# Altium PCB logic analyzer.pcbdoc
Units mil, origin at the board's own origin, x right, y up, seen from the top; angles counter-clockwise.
Board outline 1771.65 x 984.25 mil, 2 copper layers (Top Layer, Bottom Layer); 46 components, 39 nets, 224 pads, 64 vias.
Unrouted connection lines stored in the file: 47.
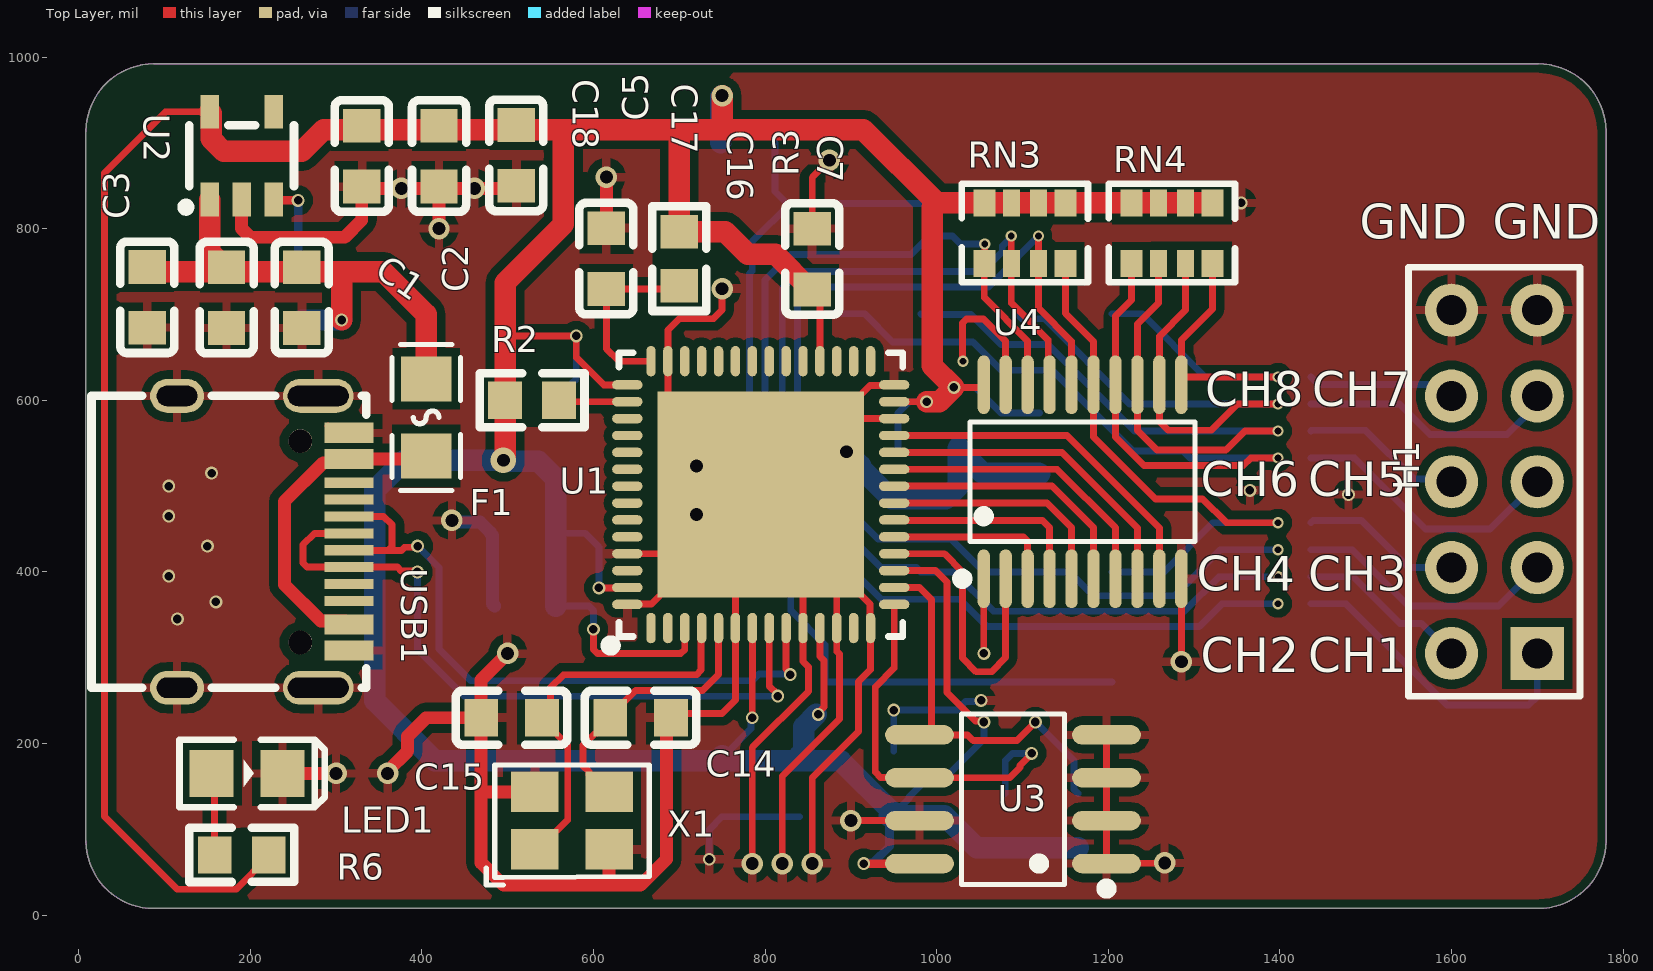
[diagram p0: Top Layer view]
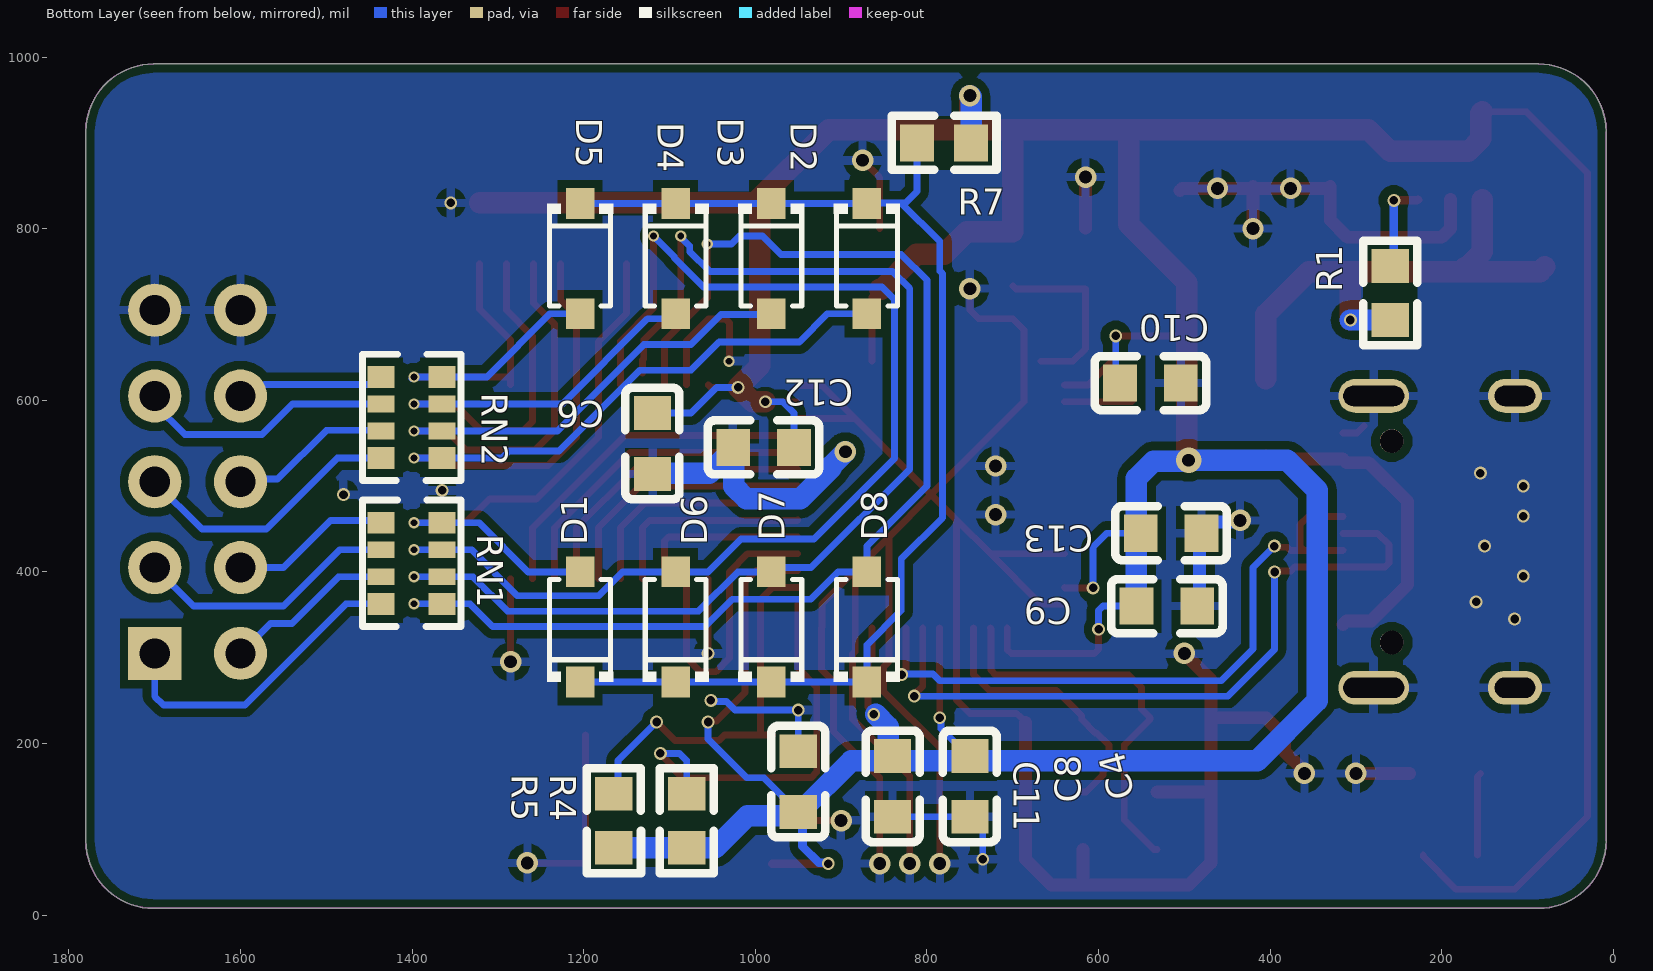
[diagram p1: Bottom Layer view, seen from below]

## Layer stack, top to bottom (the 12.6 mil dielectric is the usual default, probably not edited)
Top Solder: solder mask 0.4, Solder Resist, Dk 3.5
Top Layer: signal copper 1.4
Dielectric1: dielectric 12.6, FR-4, Dk 4.8
Bottom Layer: signal copper 1.4
Bottom Solder: solder mask 0.4, Solder Resist, Dk 3.5

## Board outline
8.51,86.42 8.51,913.2 cw(c87.25,913.2) 87.25,991.94 1701.43,991.94 cw(c1701.43,913.2) 1780.17,913.2 1780.17,86.42 cw(c1701.43,86.42) 1701.43,7.68 87.25,7.68 cw(c87.25,86.42)

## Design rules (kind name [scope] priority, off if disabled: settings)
Clearance [All] p1: gap=10 ignorepadtopadclearanceinfootprint=TRUE except(0: Arc-Hole Track-Hole SMDPad-Hole THPad-Hole Via-Hole Fill-Hole Poly-Hole Region-Hole Text-Hole; 6: Arc-SMDPad Track-SMDPad)
PolygonConnect [All] p1: connectstyle=Relief reliefconductorwidth=10 reliefentries=4 polygonreliefangle="90 Angle" airgapwidth=10
RoutingVias [All] p1: holewidth=28 width=50 viastyle="Through Hole" minholewidth=5 minwidth=10 maxholewidth=99 maxwidth=100
SolderMaskExpansion [All] p1: expansion=4 istentingtop=FALSE
Width [All] p1: maxlimit=100 minlimit=6 preferedwidth=10 minimp=50.000000 maximp=50.000000 favimp=50.000000
30 further rules are at their usual default settings.

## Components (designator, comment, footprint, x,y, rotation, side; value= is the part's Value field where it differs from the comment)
C1 "0.1u" C0603 172.5,719.57 r90 top
C2 "0.1u" C0603 260,719.57 r90 top
C3 "0.1u" C0603 80,720 r90 top
C4 "0.1u" C0603 750,150 r90 bottom
C5 "0.1u" C0603 420,884.57 r90 top
C6 "0.1u" C0603 1120,549.57 r90 bottom
C7 "0.1u" C0603 855,764.57 r270 top
C8 "0.1u" C0603 840,150 r90 bottom
C9 "0.1u" C0603 520.43,360 r0 bottom
C10 "0.1u" C0603 539.57,620 r0 bottom
C11 "0.1u" C0603 950,155.43 r270 bottom
C12 "0.1u" C0603 990.43,545 r180 bottom
C13 "0.1u" C0603 515.43,445 r0 bottom
C14 "0.1u" C0603 655,230 r180 top
C15 "0.1u" C0603 504.57,230 r0 top
C16 "0.1u" C0603 615,765 r270 top
C17 "0.1u" C0603 510,885.43 r270 top
C18 "0.1u" C0603 330,884.57 r270 top
D1 "1N4148W" SOD-123_L3.1-W1.7-LS3.7-RD 1204.29,335.83 r90 bottom
D2 "1N4148W" SOD-123_L3.1-W1.7-LS3.7-RD 870,765 r270 bottom
D3 "1N4148W" SOD-123_L3.1-W1.7-LS3.7-RD 981.43,765 r270 bottom
D4 "1N4148W" SOD-123_L3.1-W1.7-LS3.7-RD 1092.86,765 r270 bottom
D5 "1N4148W" SOD-123_L3.1-W1.7-LS3.7-RD 1204.29,765 r270 bottom
D6 "1N4148W" SOD-123_L3.1-W1.7-LS3.7-RD 1092.86,335.83 r90 bottom
D7 "1N4148W" SOD-123_L3.1-W1.7-LS3.7-RD 981.43,335.83 r90 bottom
D8 "1N4148W" SOD-123_L3.1-W1.7-LS3.7-RD 870,335.83 r90 bottom
F1 "MF-PSMF075X-2" F0805 405,580 r90 top
H1 "HDR-F-2.54_2x5" HDR-F-2.54_2X5 1650,505 r90 top
LED1 "LED-0805_R" LED0805_RED 196.35,165 r0 top
R1 "10K" R0603 260,725 r90 bottom
R2 "10k" R0603 528.5,600 r0 top
R3 "1k" R0603 700,765 r90 top
R4 "10K" R0603 1080,110 r270 bottom
R5 "10K" R0603 1165,110 r270 bottom
R6 "1k" R0603 190,70 r0 top
R7 "1k" R0603 780,900 r180 bottom
RN1 "100R" RES-ARRAY-SMD_0603-8P-L3.2-W1.6-BL 1400.79,410 r270 bottom
RN2 "100R" RES-ARRAY-SMD_0603-8P-L3.2-W1.6-BL 1400.79,580 r270 bottom
RN3 "470" RES-ARRAY-SMD_0603-8P-L3.2-W1.6-BL 1102.76,794.57 r0 top
RN4 "100K" RES-ARRAY-SMD_0603-8P-L3.2-W1.6-BL 1274.25,794.57 r0 top
U1 "CY7C68013A-56LTXC" QFN-56_L8.0-W8.0-P0.50-TL-EP 795,490 r90 top
U2 "RT9013-33GB" SOT-23-5_L3.0-W1.7-P0.95-LS2.8-BR 190,885 r270 top
U3 "AT24C02" SOP-8_L5.0-W4.0-P1.27-LS6.0-BL 1088.97,135 r90 top
U4 "74HC245PW-Q100J" TSSOP-20_L6.5-W4.4-P0.65-LS6.4-BL 1170,505 r0 top
USB1 "TYPEC-304-BCP16" USB-C-SMD_TYPEC-304-BCP16 215,435 r270 top
X1 "24MHz" OSC-SMD_4P-L3.2-W2.5-BL 575,110 r0 top

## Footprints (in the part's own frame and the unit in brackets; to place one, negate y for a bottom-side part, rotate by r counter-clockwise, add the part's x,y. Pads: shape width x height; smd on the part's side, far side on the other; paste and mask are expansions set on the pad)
C0603 [mm]
  rect 1x1.1 smd: 1(-0.9,0) 2(0.9,0)
  silkscreen extent -1.65,-0.8 1.65,0.8
F0805 [mm]
  rect 1.335x1.5 smd: 1(-1.142,0) 2(1.142,0)
  silkscreen extent -2.16,-1.02 2.16,1.02
HDR-F-2.54_2X5 [mil]
  rect 62x62 hole 35: 1(-200,-50)
  round 62 hole 35: 2(-200,50) 3(-100,-50) 4(-100,50) 5(0,-50) 6(0,50) 7(100,-50) 8(100,50) 9(200,-50) 10(200,50)
  silkscreen extent -250,-100 250,100
LED0805_RED [mil]
  rect 51.2x55.1 smd: 1(-41.35,0) 2(41.35,0)
  silkscreen extent -79,-39 91,39
OSC-SMD_4P-L3.2-W2.5-BL [mm]
  rect 1.4x1.2 smd: 1(-1.1,-0.851) 2(1.1,-0.851) 3(1.1,0.851) 4(-1.1,0.851)
  silkscreen extent -2.54,-1.91 2.29,1.65
QFN-56_L8.0-W8.0-P0.50-TL-EP [mm]
  oval 0.9x0.28 smd: 1(-3.95,3.25) 2(-3.95,2.75) 3(-3.95,2.25) 4(-3.95,1.75) 5(-3.95,1.25) 6(-3.95,0.75) 7(-3.95,0.25) 8(-3.95,-0.25) 9(-3.95,-0.75) 10(-3.95,-1.25) 11(-3.95,-1.75) 12(-3.95,-2.25) 13(-3.95,-2.75) 14(-3.95,-3.25) 29(3.95,-3.25) 30(3.95,-2.75) 31(3.95,-2.25) 32(3.95,-1.75) 33(3.95,-1.25) 34(3.95,-0.75) 35(3.95,-0.25) 36(3.95,0.25) 37(3.95,0.75) 38(3.95,1.25) 39(3.95,1.75) 40(3.95,2.25) 41(3.95,2.75) 42(3.95,3.25)
  oval 0.28x0.9 smd: 15(-3.25,-3.95) 16(-2.75,-3.95) 17(-2.25,-3.95) 18(-1.75,-3.95) 19(-1.25,-3.95) 20(-0.75,-3.95) 21(-0.25,-3.95) 22(0.25,-3.95) 23(0.75,-3.95) 24(1.25,-3.95) 25(1.75,-3.95) 26(2.25,-3.95) 27(2.75,-3.95) 28(3.25,-3.95) 43(3.25,3.95) 44(2.75,3.95) 45(2.25,3.95) 46(1.75,3.95) 47(1.25,3.95) 48(0.75,3.95) 49(0.25,3.95) 50(-0.25,3.95) 51(-0.75,3.95) 52(-1.25,3.95) 53(-1.75,3.95) 54(-2.25,3.95) 55(-2.75,3.95) 56(-3.25,3.95)
  rect 6.1x6.1 smd: 57(0,0)
  silkscreen extent -4.62,-4.2 4.2,4.59
R0603 [mm]
  rect 1x1.1 smd: 1(-0.8,0) 2(0.8,0)
  silkscreen extent -1.55,-0.8 1.55,0.81
RES-ARRAY-SMD_0603-8P-L3.2-W1.6-BL [mm]
  rect 0.65x0.8 smd: 1(-1.2,-0.9) 4(1.2,-0.9) 5(1.2,0.9) 8(-1.2,0.9)
  rect 0.5x0.8 smd: 2(-0.4,-0.9) 3(0.4,-0.9) 6(0.4,0.9) 7(-0.4,0.9)
  silkscreen extent -1.87,-1.45 1.87,1.47
SOD-123_L3.1-W1.7-LS3.7-RD [mm]
  rect 0.91x0.84 smd: 1(-1.63,0) 2(1.63,0)
  silkscreen extent -1.63,-0.98 1.4,0.98
SOP-8_L5.0-W4.0-P1.27-LS6.0-BL [mil]
  oval 22.6x80.14 smd: 1(-75,-108.97) 2(-25,-108.97) 3(25,-108.97) 4(75,-108.97) 5(75,108.97) 6(25,108.97) 7(-25,108.97) 8(-75,108.97)
  silkscreen extent -110,-115 99,60
SOT-23-5_L3.0-W1.7-P0.95-LS2.8-BR [mm]
  rect 1x0.55 smd: 1(1.3,-0.95) 2(1.3,0) 3(1.3,0.95) 4(-1.3,0.95) 5(-1.3,-0.95)
  silkscreen extent -0.9,-1.78 1.65,1.55
TSSOP-20_L6.5-W4.4-P0.65-LS6.4-BL [mm]
  oval 0.364x1.742 smd: 1(-2.925,-2.871) 2(-2.275,-2.871) 3(-1.625,-2.871) 4(-0.975,-2.871) 5(-0.325,-2.871) 6(0.325,-2.871) 7(0.975,-2.871) 8(1.625,-2.871) 9(2.275,-2.871) 10(2.925,-2.871) 11(2.925,2.871) 12(2.275,2.871) 13(1.625,2.871) 14(0.975,2.871) 15(0.325,2.871) 16(-0.325,2.871) 17(-0.975,2.871) 18(-1.625,2.871) 19(-2.275,2.871) 20(-2.925,2.871)
  silkscreen extent -3.71,-3.02 3.33,1.77
USB-C-SMD_TYPEC-304-BCP16 [mm]
  oval 1x2.1 hole 0.6 slot 1.8 at 90 deg: 13(-4.32,1.633) 14(4.32,1.633)
  oval 1x1.6 hole 0.6 slot 1.2 at 90 deg: 15(-4.32,-2.547) 16(4.32,-2.547)
  rect 0.6x1.45 smd: A1B12(-3.225,2.547) A4B9(-2.45,2.547) B1A12(3.22,2.547) B4A9(2.45,2.547)
  rect 0.3x1.45 smd: A5(-1.25,2.547) A6(-0.25,2.547) A7(0.25,2.547) A8(1.25,2.547) B5(1.75,2.547) B6(0.75,2.547) B7(-0.75,2.547) B8(-1.75,2.547)
  round 0.7 hole 0.7 unplated: ""(-2.98,1.102) ""(2.98,1.102)
  silkscreen extent -4.32,-5.08 4.32,3.05

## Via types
v1: diameter 15, hole 10, Top Layer to Bottom Layer, 31 vias
v2: diameter 25, hole 15, Top Layer to Bottom Layer, 20 vias
v3: diameter 13, hole 8, Top Layer to Bottom Layer, 12 vias
v4: diameter 30, hole 15, Top Layer to Bottom Layer, 1 vias

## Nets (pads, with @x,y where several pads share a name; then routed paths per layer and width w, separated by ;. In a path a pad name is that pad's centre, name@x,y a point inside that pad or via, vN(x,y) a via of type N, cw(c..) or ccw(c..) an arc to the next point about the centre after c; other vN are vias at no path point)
3V3: C4.2 C5.2 C6.2 C7.2 C8.2 C9.2 C10.2 C11.2 C12.2 C13.2 C17.1 C18.1 R2.1 R3.2 R4.2 R5.2 R6.2 R7.2 RN3.5 RN3.6 RN3.7 RN3.8 RN4.5 RN4.6 RN4.7 RN4.8 U1.3 U1.7 U1.11 U1.17 U1.27 U1.32 U1.43 U1.55 U2.5 U3.8 U4.20 | length 6851.9
  Top Layer w8: U2.5 101.19,936.19 30,865 30,115 115,30 183.46,30 221.5,68.03 R6.2 ; 497.01,668.51 503.51,675 v1(580,675) 580,650 612.05,617.95 U1.43 ; v1(600,333.05) 600,309.69 604.69,305 701.73,305 706.42,309.69 U1.3 ; v1(606.3,381.3) 639.06,381.3 U1.55 ; v1(785,230) 785,276.98 785.16,277.14 U1.7 ; C7.2 863.9,720.23 U1.32 ; v1(861.95,233.84) 861.95,235.74 868.82,242.61 868.82,296.63 863.9,301.56 U1.11 ; U1.17 998.58,401.42 1012,388 1012,259.58 1045.24,226.34 1053.66,226.34 v1(1055,225) ; U1.27 v1(988.27,598.27) ; v1(1020,615) 1051.92,615 1054.84,617.92 U4.20
  Top Layer w10: v1(915,60) U3.8
  Top Layer w25: U2.5 154.28,934.51 154.28,904.64 168.92,890 260,890 285.43,915.43 330,915.43 420,915.43 505,915.43 565,915.43 ; v4(495,530) 497.01,532.01 R2.1 497.01,668.51 497.01,737.01 565,805 565,915.43 ; v2(750,955) 750,915.43 ; C7.2 853.03,729.13 812.17,770 780,770 753.5,796.5 R3.2 700,910.86 704.57,915.43 ; v1(988.27,598.27) 1003.27,598.27 v1(1020,615) 995,640 995,825 1000,830 ; RN4.5 RN4.6 RN4.7 RN4.8 RN3.5 RN3.6 RN3.7 RN3.8 1000,830 ; 565,915.43 704.57,915.43 ; 704.57,915.43 750,915.43 ; 750,915.43 914.56,915.43 1000,830
  Bottom Layer w8: C13.2 555.87,445 590,445 606.3,428.7 v1(606.3,381.3) ; C9.2 595,360 600,355 v1(600,333.05) ; C10.2 580,625 v1(580,675) ; C4.2 751.97,185.43 783.66,217.13 783.66,228.66 v1(785,230) ; C11.2 951.97,120 967.65,135.68 967.65,137.65 990,160 1010,160 1055,205 v1(1055,225) ; C12.2 955,585 968.27,598.27 v1(988.27,598.27) ; v1(1020,615) 1045,615 1075,585 C6.2
  Bottom Layer w10: v1(915,60) 915.91,60.91 925.91,60.91 945,80 C11.2@945,115
  Bottom Layer w25: C9.2 555.87,445 555.87,509.13 535.96,529.04 495.96,529.04 v4(495,530) 380,530 345,495 345,250 415,180 C4.2@755.43,180 ; R7.2 748.5,953.5 v2(750,955) ; C4.2 C4.2@755.43,180 ; C8.2@840,180 888.03,180 948.03,120 C11.2 ; v1@859.64,233.84 845,219.2 845,190.43 C8.2 834.57,180 C4.2@755.43,180 ; C11.2@945,115 945.85,115.85 1009.15,115.85 1046.49,78.5 R4.2 R5.2
+5V: C1.2 C2.2 C3.2 F1.2 R1.1 U2.1 | length 615.6
  Top Layer w25: C3.2 85.43,750 310,750 ; U2.1 152.6,772.93 170.53,755 C1.2 ; v1(306.49,693.51) 306.49,746.49 310,750 ; F1.2 405,700 355,750 310,750
  Bottom Layer w25: R1.1 v1(306.49,693.51)
D1_1: D1.1 D2.1 D3.1 D4.1 D5.1 D6.1 D7.1 D8.1 R7.1 | length 1404.2
  Bottom Layer w8: R7.1 811.49,843.51 825,830 830,830 ; D1.1 D6.1 D7.1 D8.1 870,315 830,355 830,415 782,463 782,747.46 785,750.46 785,785 830,830 ; D5.1 D4.1 D3.1 871.65,829.17 870.83,830 830,830
DN: U1.9 USB1.A7 USB1.B7 | length 782.2
  Top Layer w8: USB1.A7 315.45,425 360.31,425 ; USB1.B7 355.47,464.53 365,455 365,429.69 360.31,425 ; v1(395,430) 393.66,428.66 379.97,428.66 376.31,425 360.31,425 ; U1.9 824.53,286.96 829.32,282.17 v1(829.32,280.27)
  Bottom Layer w8: v1(395,430) 420,405 420,310 457,273 785,273 792.95,280.95 828.65,280.95 v1(829.32,280.27)
DP: U1.8 USB1.A6 USB1.B6 | length 834.5
  Top Layer w8: USB1.A6 274.75,444.85 261.5,431.59 261.5,410.16 266.19,405.47 USB1.B6 371.5,405.47 375.84,401.14 393.46,401.14 v1(394.8,399.8) ; U1.8 804.84,267.05 814.8,257.1 v1(814.8,255.2)
  Bottom Layer w8: v1(394.8,399.8) 395,399.59 395,309.54 449.54,255 814.59,255 v1(814.8,255.2)
GND: C1.1 C2.1 C3.1 C4.1 C5.1 C6.1 C7.1 C8.1 C9.1 C10.1 C11.1 C12.1 C13.1 C14.1 C15.1 C16.1 C17.2 C18.2 H1.9 H1.10 LED1.2 U1.6 U1.10 U1.12 U1.14 U1.26 U1.28 U1.41 U1.53 U1.56 U1.57 U2.2 U3.1 U3.2 U3.3 U3.4 U3.7 U4.1 U4.10 U4.19 USB1.13 USB1.14 USB1.15 USB1.16 USB1.A1B12 USB1.B1A12 X1.2 X1.4 | length 5519.1
  Top Layer w8: USB1.13 USB1.13@290.75,593.6 ; USB1.A1B12@290.75,569.78 298.56,561.97 USB1.A1B12 ; U1.56 640.05,362.61 667.61,362.61 U1.57@726.1,421.1 ; U1.53 U1.57@726.1,421.1 ; C14.1@685,224.57 C14.1 695.43,235 750,235 765.47,250.47 U1.6 U1.57@765.47,460.47 ; v2(750,730) 750,705 740,695 700,695 686.73,681.73 U1.41 686.73,598.27 U1.57 ; v2(785,60) 785,195 850.82,260.82 850.82,289.18 844.21,295.79 U1.10 U1.57@844.21,440.79 ; v2(820,60) 820,161.49 886.82,228.31 886.82,304.09 883.58,307.33 U1.12 U1.57@883.58,401.42 ; v2@855,55 855,160 908.97,213.97 908.97,271.92 922.95,285.9 U1.14 922.39,335.05 922.39,362.61 U1.57@883.58,401.42 ; C7.1 855,859.39 875,879.39 v2(875,879.69) ; v2@895,115 v2(900,110) U3.7 ; U1.26 U1.57@883.58,578.58 ; U1.28 949.95,617.39 922.39,617.39 U1.57@883.58,578.58 ; v3(1030.51,645.51) 1030,646.01 1030,690.09 1034.69,694.77 1054.77,694.77 1080.43,669.11 U4.19 ; U4.1 1054.92,391.89 1054.92,305.08 v1(1055,305) ; U3.4 U3.3 U3.2 U3.1 1198.33,60.4 1265.4,60.4 v2(1265.79,60.79) ; v2@1285,295 v2(1285.16,295.16) U4.10 ; U1.57@726.1,421.1 U1.57@765.47,460.47 ; U1.57@765.47,460.47 U1.57 ; U1.57 U1.57@844.21,440.79 ; U1.57 U1.57@883.58,578.58 ; U1.57@844.21,440.79 U1.57@883.58,401.42
  Top Layer w15: U2.2 190,800 200,790 310,790 330,810 C18.2 332.28,846.85 C5.1@420,846.85 ; LED1.2 v2(300,165) ; v2(360,165) 360,167.58 383.46,191.04 383.46,208.46 405,230 C15.1 ; v2(420,800) C5.1@420,846.85 ; C5.1 C5.1@420,846.85 ; v2(500,305) 469.13,274.13 C15.1 ; C17.2@505,844.57 502.72,846.85 C5.1@420,846.85 ; X1.4 471.06,143.51 469.13,145.43 ; C16.1 v2(615,860) ; X1.2 618.31,36.69 620,35 ; C14.1@685,224.57 685,65 655,35 620,35 ; 469.13,145.43 C15.1 ; 469.13,145.43 469.13,60.87 495,35 620,35
  Bottom Layer w8: v1(735,65) 735,99.57 C4.1 C8.1 ; C11.1 v1(950,238.77) 1023.77,238.77 1033.81,248.81 1050.49,248.81 v1(1051.83,250.15) ; C12.1@1025.87,543.03 C12.1
  Bottom Layer w15: v2(435,460) 436.91,458.09 467.81,458.09 480,445.9 C13.1 482.5,442.5 482.5,362.5 C9.1
  Bottom Layer w25: v2(895,540) 911.33,523.67 911.33,521.17 947.5,485 1010.36,485 1025,499.64 1025,544.13 C12.1 ; C12.1@1025.87,543.03 1053.9,515 1119.13,515 C6.1
  other v1: 115,345 160,365 105,395 150,430 105,465 1480,490 1365,495 105,500 155,515 1355,830
  other v2: 855,60 720,466.67 720,523.33 376.14,846.85 461.36,846.85
IN0: D8.2 RN1.5 RN3.1 U4.18 | length 1400.8
  Top Layer w8: v3(1056.02,782.06) 1056.02,759.65 RN3.1 1055.52,719.48 1106.02,668.98 U4.18
  Bottom Layer w8: v3(1056.02,782.06) 1027.86,782.06 1018.36,791.55 991.55,791.55 970,770 830,770 800,740 800,500 870,430 D8.2 903.77,400 935.72,368.04 1026.96,368.04 1058.91,336.09 1306.09,336.09 1332.76,362.76 RN1.5 v3(1397.77,362.76)
IN1: D7.2 RN1.6 RN3.2 U4.17 | length 1348.4
  Top Layer w8: v3(1087.01,791.55) RN3.2 1087.01,713.45 1130,670.46 1130,648.48 1131.61,646.87 U4.17@1131.61,631.59
  Bottom Layer w8: v3(1087.01,791.55) 1087.01,790.19 1076.52,779.71 1076.52,773.56 1052.96,750 840,750 820,730 820,520 935,405 976.43,405 D7.2 1020.46,400 1066.37,354.09 1289.09,354.09 1329.25,394.25 RN1.6 v3(1397.77,394.25)
IN2: D6.2 RN1.7 RN3.3 U4.16 | length 1335.3
  Top Layer w8: v3(1118.51,791.55) RN3.3 1118.51,707.4 1157.2,668.71 U4.16
  Bottom Layer w8: v3(1118.51,791.55) 1094.52,767.56 1094.52,766.11 1060.42,732 852.58,732 838,717.42 838,532 931.66,438.34 1016.66,438.34 1055,400 D6.2 1155,400 1182.91,372.09 1277.09,372.09 1330.75,425.75 RN1.7 v3(1397.77,425.75)
IN3: D1.2 RN1.8 RN3.4 U4.15 | length 689.1
  Top Layer w8: RN3.4 1150,701.37 1182.8,668.57 U4.15 1182.8,557.21 1255,485 1310,485 1337.76,457.24 v3(1397.76,457.24)
  Bottom Layer w8: D1.2 1265,400 1322.24,457.24 RN1.8 v3(1397.76,457.24)
IN4: D2.2 RN2.5 RN4.1 U4.14 | length 1013.9
  Top Layer w8: RN4.1 1227.01,717.01 1208.39,698.39 U4.14 1208.39,557.07 1241.46,524 1357.33,524 1366.09,532.76 v3(1397.77,532.76)
  Bottom Layer w8: D2.2 915.85,700.83 948.77,667.91 1042.09,667.91 1075,635 1134.54,635 1228.91,540.63 1287.32,540.63 1295.2,532.76 v3(1397.77,532.76)
IN5: D3.2 RN2.6 RN4.2 U4.13 | length 859.8
  Top Layer w8: RN4.2 1258.5,713.5 1233.98,688.98 1233.98,564.82 1256.8,542 1337,542 1359.25,564.25 v3(1397.77,564.25)
  Bottom Layer w8: D3.2 982.26,700 1040,700 1075,665 1130,665 1230.75,564.25 RN2.6 v3(1397.77,564.25)
IN6: D4.2 RN2.7 RN4.3 U4.12 | length 700
  Top Layer w8: RN4.3 1290,705 1259.57,674.57 1259.57,575.43 1270,565 1320,565 1350.75,595.75 v3(1397.77,595.75)
  Bottom Layer w8: D4.2 1098.68,695 1125.46,695 1224.71,595.75 RN2.7 v3(1397.77,595.75)
IN7: D5.2 RN2.8 RN4.4 U4.11 | length 497.1
  Top Layer w8: U4.11 U4.11@1285.16,624.31 ; RN4.4 1321.49,706.49 1285.16,670.16 U4.11@1285.16,624.31 ; v3(1397.76,627.24) 1288.08,627.24 U4.11@1285.16,624.31
  Bottom Layer w8: D5.2 1239.17,700.83 1312.76,627.24 RN2.8 v3(1397.76,627.24) v3@1400,625
P0: H1.1 RN1.4 | length 366.7
  Bottom Layer w8: RN1.4 1477.24,362.76 1595,245 1690,245 1700,255 H1.1
P1: H1.2 RN1.3 | length 200.7
  Bottom Layer w8: RN1.3 1485.75,394.25 1540,340 1565,340 H1.2
P2: H1.3 RN1.2 | length 309.7
  Bottom Layer w8: RN1.2 1484.25,425.75 1550,360 1655,360 H1.3
P3: H1.4 RN1.1 | length 187.7
  Bottom Layer w8: RN1.1 1438.97,460 1495,460 1550,405 H1.4
P4: H1.5 RN2.4 | length 320.8
  Bottom Layer w8: RN2.4 1487.24,532.76 1570,450 1645,450 H1.5
P5: H1.6 RN2.3 | length 188.9
  Bottom Layer w8: RN2.3 1436.97,565 1500,565 1557,508 1597,508 H1.6
P6: H1.7 RN2.2 | length 303.1
  Bottom Layer w8: RN2.2 1539.25,595.75 1575,560 1665,560 1700,595 H1.7
P7: H1.8 RN2.1 | length 173
  Bottom Layer w8: RN2.1 1445.01,618.45 1571.94,618.45 1585.39,605 H1.8
R6_1: LED1.1 R6.1 | length 96.5
  Top Layer w8: LED1.1 158.51,161.49 R6.1
SCL: R4.1 U1.15 U3.6 | length 475.6
  Top Layer w8: U1.15 950.51,288 928.44,265.93 928.44,166.65 934.69,160.41 979.59,160.41 U3.6 1085,160 1097.19,172.19 1097.19,174.34 1110.71,187.87 v1(1110.71,188.39)
  Bottom Layer w8: R4.1 1080,180 1088.39,188.39 v1(1110.71,188.39)
SDA: R5.1 U1.16 U3.5 | length 458.1
  Top Layer w8: U1.16 980,381.73 994,367.73 994,210.74 U3.5@993.26,210 ; U3.5 U3.5@993.26,210 ; v1(1115,225) 1093.5,203.5 1042.62,203.5 1036.12,210 U3.5@993.26,210
  Bottom Layer w8: v1(1115,225) 1160,180 1160,146.49 R5.1
U1_4: C15.2 U1.4 X1.1 | length 456.5
  Top Layer w8: X1.1 535.63,76.5 570,110.87 570,198.03 540,228.03 C15.2 550,240 550,265 565,280 720,280 725.52,285.52 725.52,333.91 U1.4
U1_5: C14.2 U1.5 X1.3 | length 317.7
  Top Layer w8: X1.3 614.37,143.51 594.75,163.13 594.75,167.07 588,173.81 588,198 602.35,212.35 603.88,212.35 619.57,228.03 619.57,231.97 649.25,261.65 727.11,261.65 745.79,280.33 U1.5
U1_18: U1.18 U4.2 | length 344.5
  Top Layer w8: U1.18 1008.9,421.1 1030,400 1030,299.59 1046.09,283.5 1063.91,283.5 1080.43,300.03 U4.2
U1_19: U1.19 U4.3 | length 201.6
  Top Layer w8: U1.19 1101.34,440.79 1106.02,436.1 U4.3
U1_20: U1.20 U4.4 | length 244.5
  Top Layer w8: U1.20 950.98,460 1123.45,460 1131.61,451.84 U4.4
U1_21: U1.21 U4.5 | length 278.2
  Top Layer w8: U1.21 1128.75,480.16 1157.2,451.7 U4.5
U1_22: U1.22 U4.6 | length 312
  Top Layer w8: U1.22 950.67,500 1134.36,500 1182.8,451.57 U4.6
U1_23: U1.23 U4.7 | length 345.5
  Top Layer w8: U1.23 1140.29,519.53 1208.39,451.43 U4.7
U1_24: U1.24 U4.8 | length 379.2
  Top Layer w8: U1.24 1146.06,539.21 1233.98,451.3 U4.8
U1_25: U1.25 U4.9 | length 412.9
  Top Layer w8: U1.25 1151.83,558.9 1259.57,451.16 U4.9
U1_42: C16.2 R3.1 U1.42 | length 214.3
  Top Layer w8: U1.42 629.49,645.51 615,660 C16.2 696.06,729.57 R3.1
U1_44: R2.2 U1.44 | length 80.2
  Top Layer w8: R2.2 561.73,598.27 U1.44
U2_3: R1.2 U2.3 | length 106.9
  Top Layer w10: U2.3 228.35,832.87 v1(255.78,832.87)
  Bottom Layer w10: v1(255.78,832.87) 255.78,760.71 R1.2
USB1_B4A9: F1.1 USB1.A4B9 USB1.B4A9 | length 378.6
  Top Layer w15: USB1.B4A9 310.98,342.86 282.14,342.86 240,385 240,482.15 285,527.15 310.98,527.15 USB1.A4B9 401.44,531.46 F1.1
pads on no net: U1.1 U1.2 U1.13 U1.29 U1.30 U1.31 U1.33 U1.34 U1.35 U1.36 U1.37 U1.38 U1.39 U1.40 U1.45 U1.46 U1.47 U1.48 U1.49 U1.50 U1.51 U1.52 U1.54 U2.4 USB1. USB1.A5 USB1.A8 USB1.B5 USB1.B8

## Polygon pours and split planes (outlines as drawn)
GND on Top Layer "GND_L01_P000" (solid, remove dead copper, pour order 0): 0,1020 1735,1020 1800,955 1800,35 1765,0 0,0
GND on Bottom Layer "GND_L02_P001" (solid, remove dead copper, pour order 1): 0,1050 1715,1050 1835,930 1835,30 1805,0 0,0

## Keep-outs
Keep-Out Layer:
  the board outline again, w0.5

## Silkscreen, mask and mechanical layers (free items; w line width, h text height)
Top Overlay:
  text "GND" at 1493,788 h40
  text "GND" at 1648,788 h40
  text "CH8" at 1313,593 h40
  text "CH7" at 1438,593 h40
  text "CH6" at 1308,488 h40
  text "CH5" at 1433,488 h40
  text "CH4" at 1303,378 h40
  text "CH3" at 1433,378 h40
  text "CH2" at 1308,283 h40
  text "CH1" at 1433,283 h40
Mechanical 1:
  the board outline again, w0.5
